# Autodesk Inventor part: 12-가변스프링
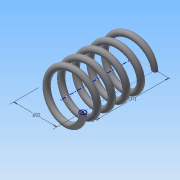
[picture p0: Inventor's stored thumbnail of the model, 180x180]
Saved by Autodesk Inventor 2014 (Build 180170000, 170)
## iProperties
Created: 2015-09
Part Number: 12-가변스프링
Material: 강철, 탄소
Document SubType Name: Modeling
Designer: study
Density: 7.87 g/cm^3
Appearance: 반연마
Mass: 18.7685 g
Surface Area: 32.4107 cm^2
Volume: 2.38482 cm^3
Author: study
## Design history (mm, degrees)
sketch "스케치1"
  geometry: L1 (0, 0)-(11, 0); L2 (11, 0)-(11, 26.495); L3 (11, 26.495)-(0, 26.495); L4 (0, 26.495)-(0, 0); C1 r 1.5 at (11, 0); 1 further point
  constraints: 8 end point, 2 coincident, 2 parallel, 1 centre point, 1 horizontal, 1 perpendicular
  dimensions: "d0" = 22 diameter of L2 L4; "d1" = 26.4955 distance between parallel lines of L1 L3 (derived); "d2" = 3 diameter of C1
feature "코일1" sketch "스케치1" pitch "d3" = 10; turns "d5" = 5; dims "d4" = 26.4955 (= d1), "d6" = 0, angle "d7" = 90 deg, angle "d8" = 90 deg, "d9" = 0, "d10" = 0
node "작업 평면1"
sketch "스케치2"
  geometry: L1 (-12.5, 0)-(-9.5, 0) reference; 1 further point
  constraints: 1 horizontal alignment
extrude "돌출1" cut sketch "스케치2" stored distance "d12" = 10; taper "d13" = 0 deg
node "작업 평면2"
sketch "스케치3"
  geometry: L1 (-9.5, 0)-(-12.5, 0) reference; 1 further point
  constraints: 1 horizontal alignment
extrude "돌출2" cut sketch "스케치3" stored distance "d15" = 10; taper "d16" = 0 deg
node "솔리드1"
node "절단 모서리 투영1"
node "절단 모서리 투영2"
other parameters: "d11" = 0, "d14" = 26.4955 (= d1)
